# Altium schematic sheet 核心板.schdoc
size 420 x 297 mm; Symbol: Drawing-Symbol_A4; Company: 嘉立创EDA; Version: V1.0; Page Size: A4; @Project Name: 短信息编辑器; @Update Date: 2026-06-04; @Create Date: 2026-06-04; Device: Drawing-Symbol_A4; @Board Name: Board1; @Page Name: P1; @Create Time: 14:51:12; @Page Count: 1; @Page No: 1; @Schematic Name: Schematic1; @Update Time: 14:51:12; @Assembly Variant: Basic; Border: 1; Title Block Position: 3; Size: A4; Width: 1655; Height: 1170; Region Start: 1; X Region Count: 6; Y Region Count: 4; Blade Width: 10
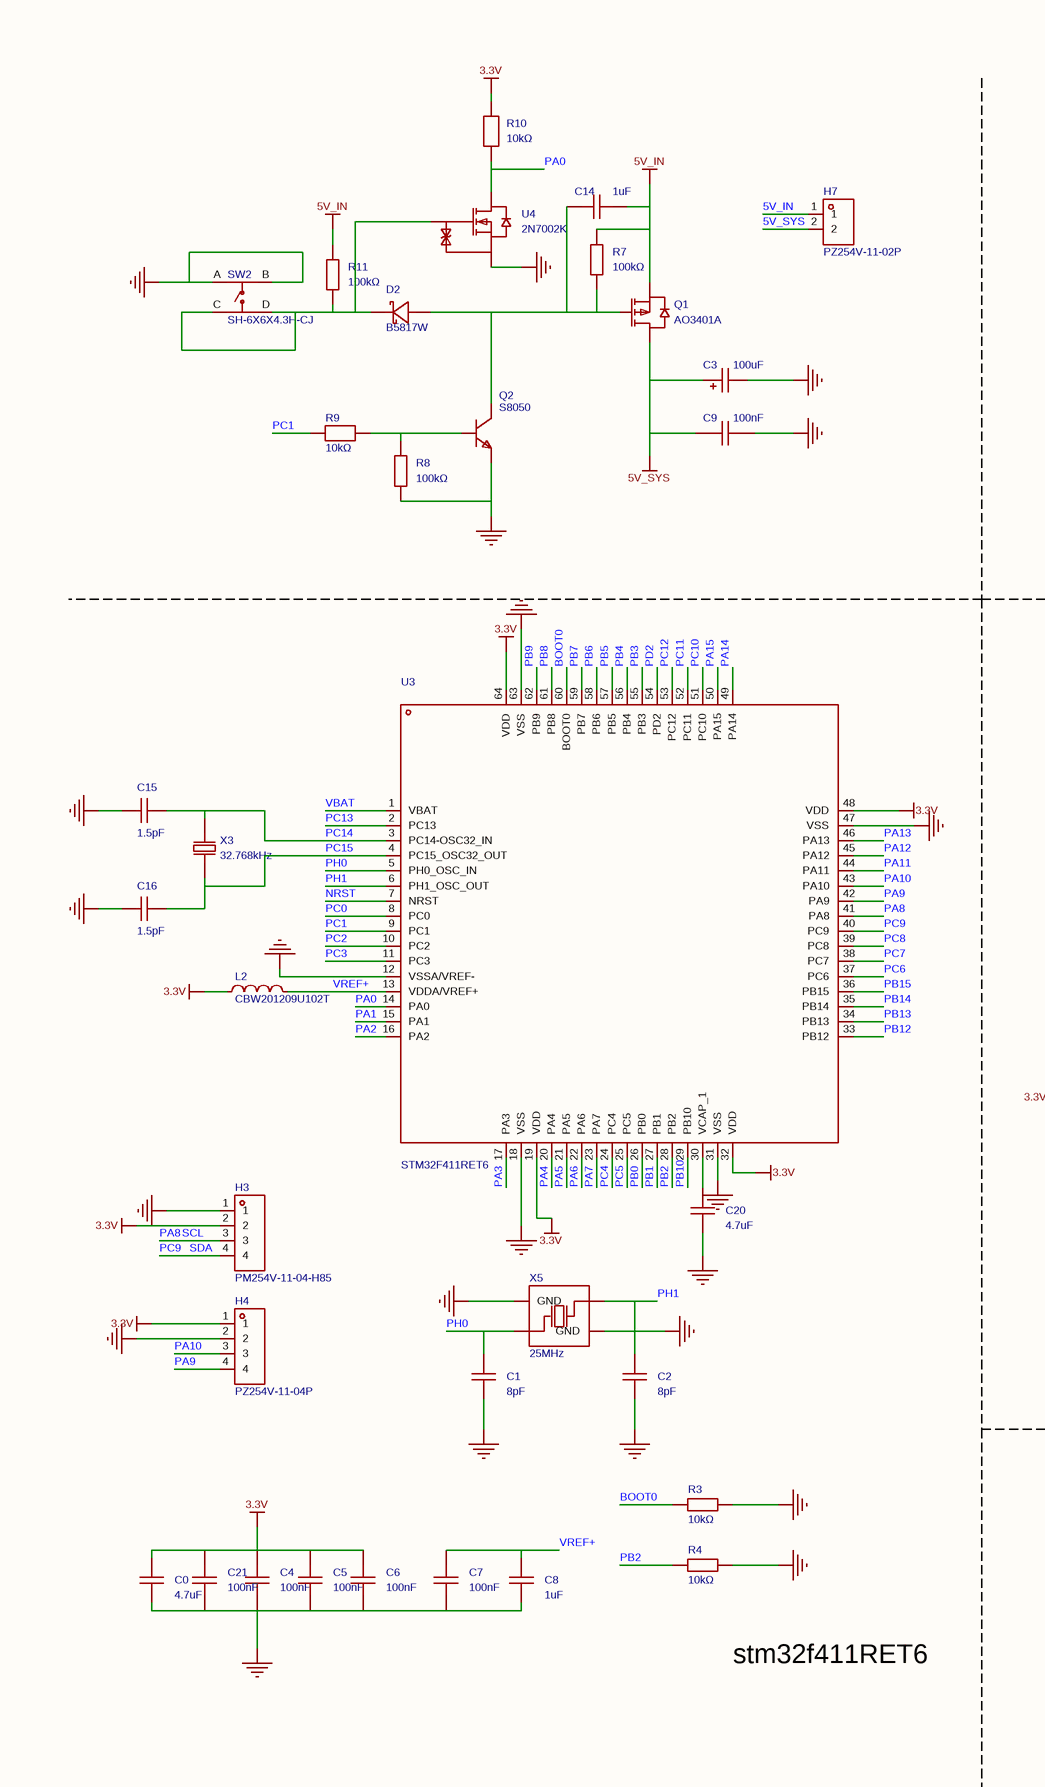
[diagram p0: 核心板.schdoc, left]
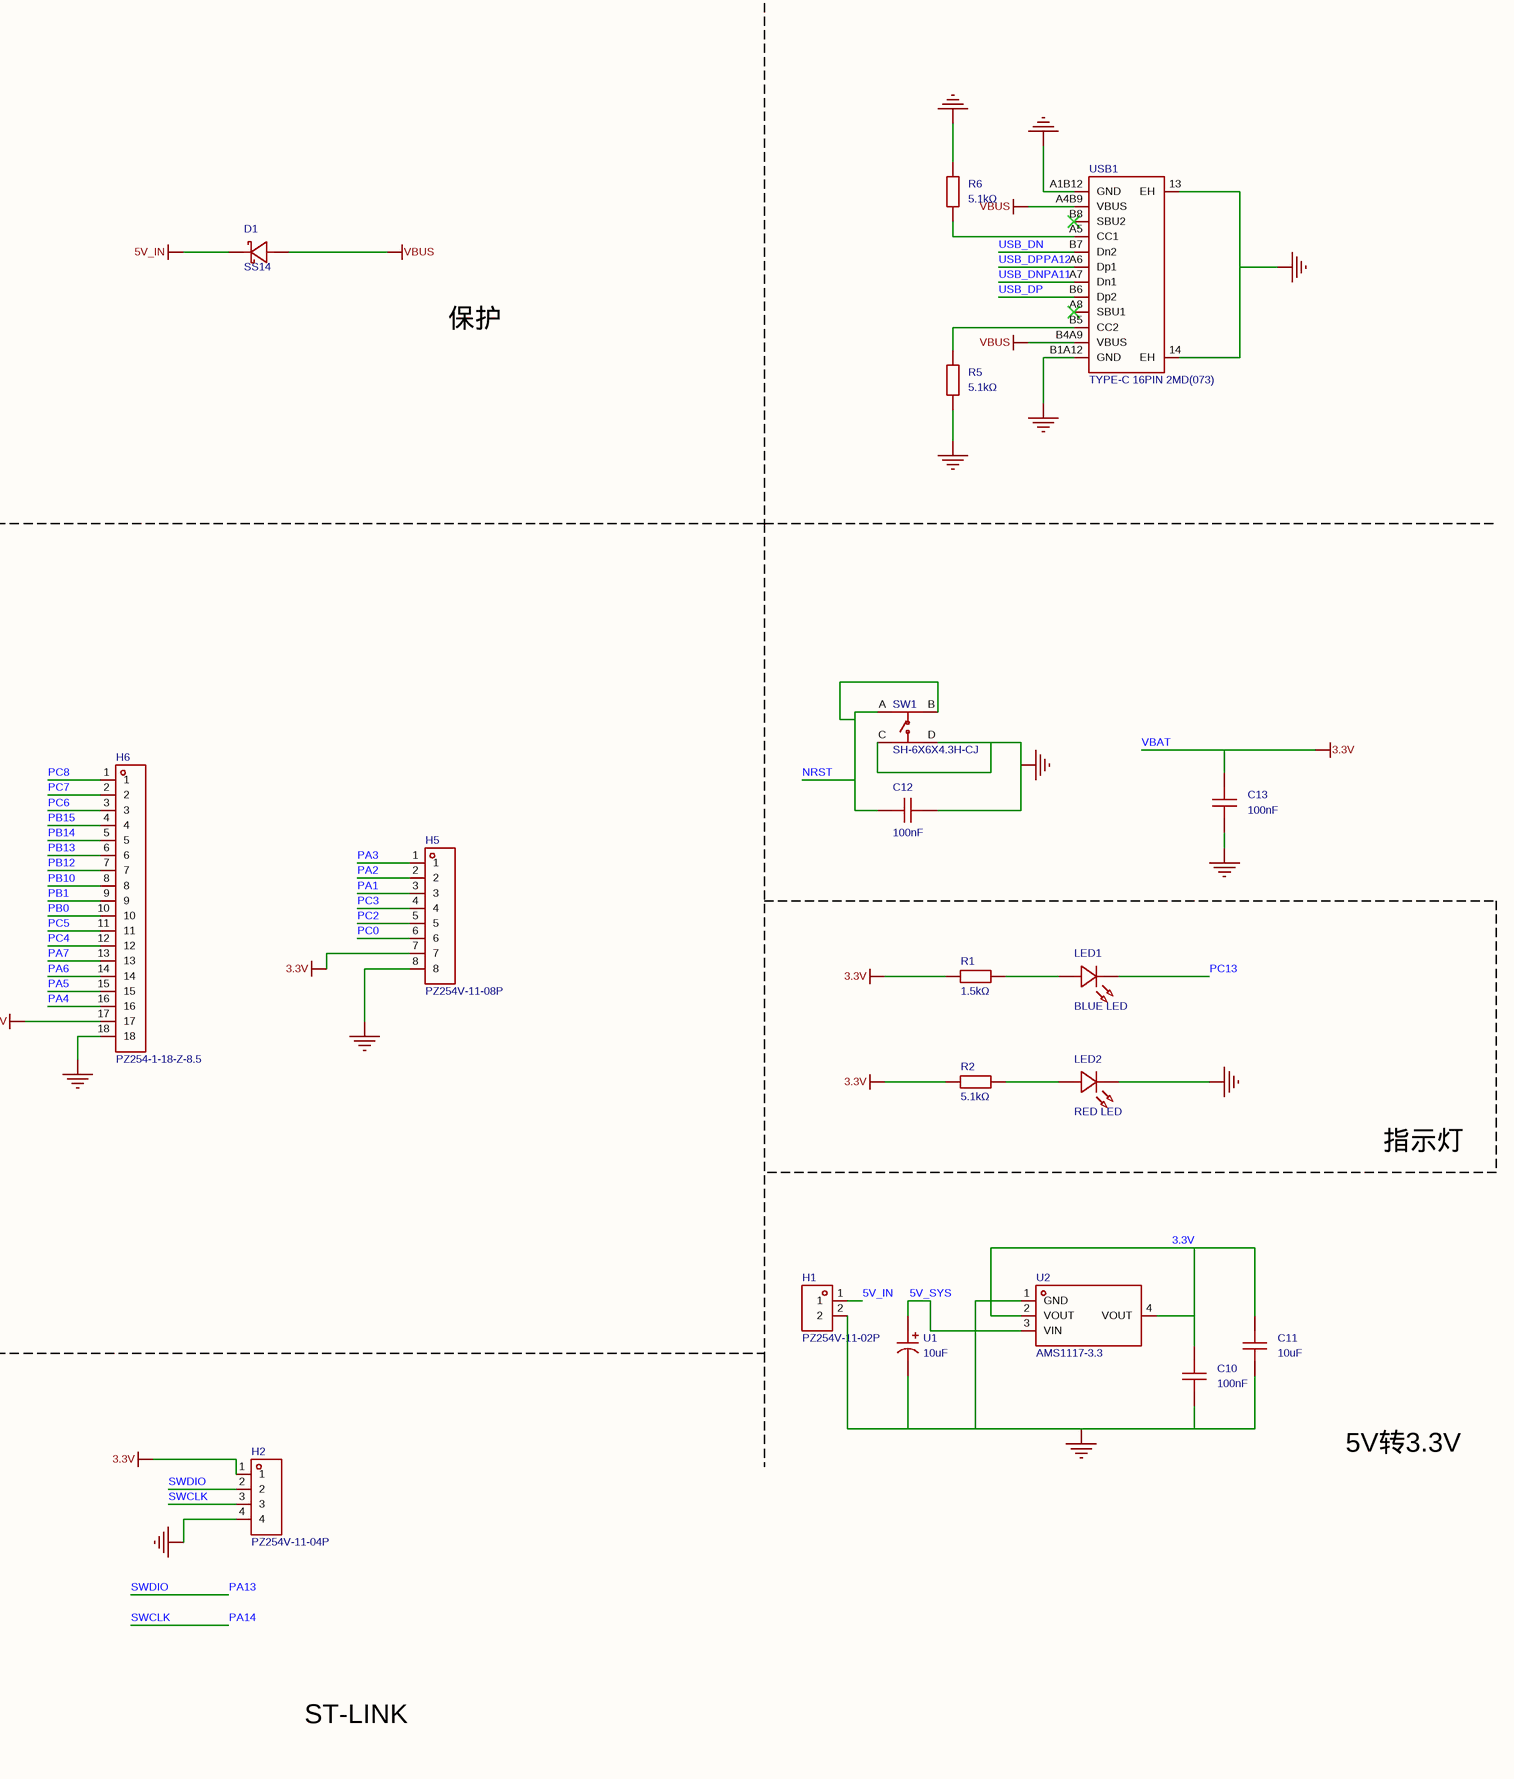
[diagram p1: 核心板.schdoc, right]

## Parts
C0  4.7uF  [C0805]
C1  8pF  [C0603]
C2  8pF  [C0603]
C3  100uF  [CASE-B_3528]
C4  100nF  [C0805]
C5  100nF  [C0805]
C6  100nF  [C0805]
C7  100nF  [C0805]
C8  1uF  [C0805]
C9  100nF  [C0805]
C10  100nF  [C0805]
C11  10uF  [C0805]
C12  100nF  [C0805]
C13  100nF  [C0805]
C14  1uF  [C0805]
C15  1.5pF  [C0603]
C16  1.5pF  [C0603]
C20  4.7uF  [C0805]
C21  100nF  [C0805]
D1  SS14  [SMA_L4.3-W2.6-LS5.0-FD]
D2  B5817W  [SOD-123_L2.7-W1.6-LS3.7-FD]
H1  PZ254V-11-02P  [HDR-TH_2P-P2.54-V-M]
H2  PZ254V-11-04P  [HDR-TH_4P-P2.54-V-M]
H3  PM254V-11-04-H85  [HDR-TH_4P-P2.54-V-F]
H4  PZ254V-11-04P  [HDR-TH_4P-P2.54-V-M]
H5  PZ254V-11-08P  [HDR-TH_8P-P2.54-V-M]
H6  PZ254-1-18-Z-8.5  [HDR-TH_18P-P2.54-V-M]
H7  PZ254V-11-02P  [HDR-TH_2P-P2.54-V-M]
L2  CBW201209U102T  [L0805]
LED1  BLUE LED  [LED0805-RD_BLUE]
LED2  RED LED  [LED0805-R-RD_RED]
Q1  AO3401A  [SOT-23_L2.9-W1.3-P1.90-LS2.4-BR]
Q2  S8050  [SOT-23-3_L2.9-W1.3-P1.90-LS2.3-BR]
R1  1.5kΩ  [R0805]
R2  5.1kΩ  [R0805]
R3  10kΩ  [R0805]
R4  10kΩ  [R0805]
R5  5.1kΩ  [R0805]
R6  5.1kΩ  [R0805]
R7  100kΩ  [R0805]
R8  100kΩ  [R0805]
R9  10kΩ  [R0805]
R10  10kΩ  [R0805]
R11  100kΩ  [R0805]
SW1  SH-6X6X4.3H-CJ  [SW-TH_SH-6X6X4.3H-CJ]
SW2  SH-6X6X4.3H-CJ  [SW-TH_SH-6X6X4.3H-CJ]
U1  10uF  [CAP-SMD_L2.0-W1.3-FD]
U2  AMS1117-3.3  [SOT-223-3_L6.5-W3.4-P2.30-LS7.0-BR]
U3  STM32F411RET6  [LQFP-64_L10.0-W10.0-P0.50-LS12.0-BL]
U4  2N7002K  [SOT-23-3_L2.9-W1.3-P0.95-LS2.4-BR]
USB1  TYPE-C 16PIN 2MD(073)  [USB-C-SMD_TYPE-C-16PIN-2MD-073]
X3  32.768kHz  [CRYSTAL-SMD_L3.2-W1.5-1]
X5  25MHz  [CRYSTAL-SMD_4P-L3.2-W2.5-BL]

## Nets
3.3V: C0.2 C4.2 C5.2 C6.2 C10.2 C11.2 C13.2 C21.2 H2.1 H3.2 H4.1 H5.7 H6.17 L2.1 R1.1 R2.1 R10.2 U2.2(VOUT) U2.4(VOUT) U3.1(VBAT) U3.19(VDD) U3.32(VDD) U3.48(VDD) U3.64(VDD)  [also labelled VBAT]
5V_IN: C14.1 D1.2(K) H1.1 H7.1 Q1.2(S) R7.2 R11.2
5V_SYS: C3.1 C9.2 H7.2 Q1.3(D) U1.1 U2.3(VIN)
GND: C0.1 C1.1 C2.1 C3.2 C4.1 C5.1 C6.1 C7.1 C8.1 C9.1 C10.1 C11.1 C12.1 C13.1 C15.1 C16.1 C20.1 C21.1 H1.2 H2.4 H3.1 H4.2 H5.8 H6.18 LED2.2(C) Q2.2(E) R3.2 R4.2 R5.1 R6.2 R8.1 SW1.C SW1.D SW2.A SW2.B U1.2 U2.1(GND) U3.12(VSSA/VREF-) U3.18(VSS) U3.31(VSS) U3.47(VSS) U3.63(VSS) U4.2(S) USB1.13(EH) USB1.14(EH) USB1.A1B12(GND) USB1.B1A12(GND) X5.2(GND) X5.4(GND)
VBUS: D1.1(A) USB1.A4B9(VBUS) USB1.B4A9(VBUS)
BOOT0: R3.1 U3.60(BOOT0)
NRST: C12.2 SW1.A SW1.B U3.7(NRST)
PA0: R10.1 U3.14(PA0) U4.3(D)
PA1: H5.3 U3.15(PA1)
PA2: H5.2 U3.16(PA2)
PA3: H5.1 U3.17(PA3)
PA4: H6.16 U3.20(PA4)
PA5: H6.15 U3.21(PA5)
PA6: H6.14 U3.22(PA6)
PA7: H6.13 U3.23(PA7)
PA8: H3.3 U3.41(PA8)  [also labelled SCL]
PA9: H4.4 U3.42(PA9)
PA10: H4.3 U3.43(PA10)
PA11: U3.44(PA11) USB1.A7(Dn1) USB1.B7(Dn2)  [also labelled USB_DN]
PA12: U3.45(PA12) USB1.A6(Dp1) USB1.B6(Dp2)  [also labelled USB_DP]
PA13: H2.2 U3.46(PA13)  [also labelled SWDIO]
PA14: H2.3 U3.49(PA14)  [also labelled SWCLK]
PA15: U3.50(PA15)
PB0: H6.10 U3.26(PB0)
PB1: H6.9 U3.27(PB1)
PB2: R4.1 U3.28(PB2)
PB3: U3.55(PB3)
PB4: U3.56(PB4)
PB5: U3.57(PB5)
PB6: U3.58(PB6)
PB7: U3.59(PB7)
PB8: U3.61(PB8)
PB9: U3.62(PB9)
PB10: H6.8 U3.29(PB10)
PB12: H6.7 U3.33(PB12)
PB13: H6.6 U3.34(PB13)
PB14: H6.5 U3.35(PB14)
PB15: H6.4 U3.36(PB15)
PC0: H5.6 U3.8(PC0)
PC1: R9.1 U3.9(PC1)
PC2: H5.5 U3.10(PC2)
PC3: H5.4 U3.11(PC3)
PC4: H6.12 U3.24(PC4)
PC5: H6.11 U3.25(PC5)
PC6: H6.3 U3.37(PC6)
PC7: H6.2 U3.38(PC7)
PC8: H6.1 U3.39(PC8)
PC9: H3.4 U3.40(PC9)  [also labelled SDA]
PC10: U3.51(PC10)
PC11: U3.52(PC11)
PC12: U3.53(PC12)
PC13: LED1.1(K) U3.2(PC13)
PC14: C15.2 U3.3(PC14-OSC32_IN) X3.2
PC15: C16.2 U3.4(PC15_OSC32_OUT) X3.1
PD2: U3.54(PD2)
PH0: C1.2 U3.5(PH0_OSC_IN) X5.1(OSC1)
PH1: C2.2 U3.6(PH1_OSC_OUT) X5.3(OSC2)
VREF+: C7.2 C8.2 L2.2 U3.13(VDDA/VREF+)
NetC14_2: C14.2 D2.1(A) Q1.1(G) Q2.3(C) R7.1
NetC20_2: C20.2 U3.30(VCAP_1)
NetD2_2: D2.2(K) R11.1 SW2.C SW2.D U4.1(G)
NetLED1_2: LED1.2(A) R1.2
NetLED2_1: LED2.1(A) R2.2
NetQ2_1: Q2.1(B) R8.2 R9.2
NetR5_2: R5.2 USB1.B5(CC2)
NetR6_1: R6.1 USB1.A5(CC1)

Not connected (* = marked no-connect by the designer): USB1 A8(SBU1)* B8(SBU2)*

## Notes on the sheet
- 保护
- 指示灯
- 5V转3.3V
- stm32f411RET6
- ST-LINK

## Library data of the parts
C0 C20 = CL21A475KAQNNNE: 容值:4.7uF;精度:±10%;额定电压:25V;温度系数:X5R;; Manufacturer: SAMSUNG(三星); AddInBom: yes; ModelId: 1ba041120af144c991958decab20d2410819f05c4eef4c71ace90d822a990e87; ModelName: C0805_L2.0-W1.3-H1.3; ModelTransform: 78.74,51.181,0,0,0,0,0,0.0005,0; Tolerance: ±10%; Voltage Rating: 25V; Temperature Coefficient: X5R
C1 C2 = 0603CG8R0C500NT: 容值:8pF;额定电压:50V;温度系数:C0G;; Manufacturer: FH(风华); Symbol: 0603CG8R0C500NT_C36508; AddInBom: yes; ModelId: ac125912035d415993ca9572d50418b10819f05c4eef4c71ace90d822a990e87; ModelName: C0603_L1.6-W0.8-H0.8; ModelTransform: 62.992,31.496,0,0,0,0,0,0,0; Voltage Rating: 50V; Temperature Coefficient: C0G
C3 = TAJB107K006RNJ: 容值:100uF;精度:±10%;额定电压:6.3V;等效串联电阻(ESR):1.7Ω@100kHz;; Manufacturer: Kyocera AVX; AddInBom: yes; ModelId: b77bd53aeda446d2bdd09b0fdaf9418a0819f05c4eef4c71ace90d822a990e87; ModelName: CASE-B_L3.5-W2.8-H1.9; ModelTransform: 145.669,110.236,0,0,0,0,0,0,0; Tolerance: ±10%; Voltage Rating: 6.3V
C4-C7 C10 C12 C13 = CL21B104KBCNNNC: 容值:100nF;精度:±10%;额定电压:50V;温度系数:X7R;; Manufacturer: SAMSUNG(三星); AddInBom: yes; ModelId: 1ba041120af144c991958decab20d2410819f05c4eef4c71ace90d822a990e87; ModelName: C0805_L2.0-W1.3-H1.3; ModelTransform: 78.74,51.181,0,0,0,0,0,0.0005,0; Tolerance: ±10%; Voltage Rating: 50V; Temperature Coefficient: X7R
C8 = CL21B105KAFNNNE: 容值:1uF;精度:±10%;额定电压:25V;温度系数:X7R;; Manufacturer: SAMSUNG(三星); AddInBom: yes; ModelId: 1ba041120af144c991958decab20d2410819f05c4eef4c71ace90d822a990e87; ModelName: C0805_L2.0-W1.3-H1.3; ModelTransform: 78.74,51.181,0,0,0,0,0,0.0005,0; Tolerance: ±10%; Voltage Rating: 25V; Temperature Coefficient: X7R
C9 C21 = CL21B104KBCNNNC: 容值:100nF;精度:±10%;额定电压:50V;温度系数:X7R;; Manufacturer: SAMSUNG(三星); 3D Model: 1ba041120af144c991958decab20d2410819f05c4eef4c71ace90d822a990e87; 3D Model Transform: 78.74,51.181,0,0,0,0,0,0.0005,0; Tolerance: ±10%; Voltage Rating: 50V; Temperature Coefficient: X7R; AddInBom: yes; ModelName: C0805_L2.0-W1.3-H1.3
C11 = CGA0805X5R106K500MT: 容值:10uF;精度:±10%;额定电压:50V;温度系数:X5R;; Manufacturer: HRE(芯声); AddInBom: yes; ModelId: 1ba041120af144c991958decab20d2410819f05c4eef4c71ace90d822a990e87; ModelName: C0805_L2.0-W1.3-H1.3; ModelTransform: 78.74,51.181,0,0,0,0,0,0.0005,0; Tolerance: ±10%; Voltage Rating: 50V; Temperature Coefficient: X5R
C14 = CGA0805X7R105K500MT: 容值:1uF;精度:±10%;额定电压:50V;温度系数:X7R;; Manufacturer: HRE(芯声); AddInBom: yes; ModelId: 1ba041120af144c991958decab20d2410819f05c4eef4c71ace90d822a990e87; ModelName: C0805_L2.0-W1.3-H1.3; ModelTransform: 78.74,51.181,0,0,0,0,0,0.0005,0; Tolerance: ±10%; Voltage Rating: 50V; Temperature Coefficient: X7R
C15 C16 = 0603CG1R5C500NT: 容值:1.5pF;额定电压:50V;温度系数:C0G;; Manufacturer: FH(风华); AddInBom: yes; ModelId: ac125912035d415993ca9572d50418b10819f05c4eef4c71ace90d822a990e87; ModelName: C0603_L1.6-W0.8-H0.8; ModelTransform: 62.992,31.496,0,0,0,0,0,0,0; Voltage Rating: 50V; Temperature Coefficient: C0G
D1 = SS14_C7420316: 二极管配置:独立式;正向压降(Vf):550mV@1.0A;直流反向耐压(Vr):40V;整流电流:1A;; Manufacturer: R+O(宏嘉诚); AddInBom: yes; ModelId: 7e24bebe6cd74171ae8c9de6fc5b78aa0819f05c4eef4c71ace90d822a990e87; ModelTransform: 198.4248,103.5431,0,180,0,0,-0.001,0,0; Diode Configuration: 独立式; Voltage - DC Reverse(Vr): 40V; Current - Rectified: 1A; Reverse Leakage Current (Ir): 200uA@40V; Operating Junction Temperature Range: -55℃~+150℃; Non-Repetitive Peak Forward Surge Current: 30A
D2 = B5817W_C7420328: 二极管配置:独立式;正向压降(Vf):450mV@1.0A;直流反向耐压(Vr):20V;整流电流:1A;; Manufacturer: R+O(宏嘉诚); AddInBom: yes; ModelId: 5054d9b7be8b429dad093a54b517b4dd0819f05c4eef4c71ace90d822a990e87; ModelTransform: 145.669,61.024,0,0,0,0,0,0,0; Diode Configuration: 独立式; Voltage - DC Reverse(Vr): 20V; Current - Rectified: 1A; Reverse Leakage Current (Ir): 1mA@20V; Operating Junction Temperature Range: -55℃~+150℃
H1 = PZ254V-11-02P: 插针结构:1x2P;间距:2.54mm;行距:-;圆针/方针:方针;安装方式:直插;排数:单排;总PIN位数:2P;额定电流:3A;额定电压:250V;配合针长度:6mm;塑高:2.5mm;端接针长度:3mm;触头材质:黄铜;触头镀层:-;工作温度:-40℃~+105℃;颜色:黑色;; Manufacturer: XFCN(兴飞); AddInBom: yes; ModelId: e35305ec3aa84b66b849f914b715e73f0819f05c4eef4c71ace90d822a990e87; ModelName: HDR2.54-M-LI-1X2P; ModelTransform: 200,100,0,0,0,0,0,0,-118.11; Pin Structure: 1x2P; Pitch: 2.54mm; Circluar Pins/Square Pins: 方针; Current Rating: 3A; Voltage Rating (Max): 250V
H2 = PZ254V-11-04P: 插针结构:1x4P;间距:2.54mm;行距:-;圆针/方针:方针;安装方式:直插;排数:单排;总PIN位数:4P;额定电流:3A;额定电压:250V;配合针长度:6mm;塑高:2.5mm;端接针长度:3mm;触头材质:-;工作温度:-40℃~+105℃;颜色:黑色;; Manufacturer: XFCN(兴飞); Symbol: PZ254V-11-04P_C2691448; AddInBom: yes; ModelId: 112f4d05e8d64e99ab9a333894bea4f90819f05c4eef4c71ace90d822a990e87; ModelName: HDR-TH_4P-P2.54-M-LI-1X4P; ModelTransform: 399.999,104.7242,0,0,0,0,0,0,-118.11; Pin Structure: 1x4P; Pitch: 2.54mm; Circluar Pins/Square Pins: 方针; Current Rating: 3A; Voltage Rating (Max): 250V
H3 = PM254V-11-04-H85: 插孔结构:1x4P;间距:2.54mm;行距:-;圆孔/方孔:方孔;安装方式:直插;排数:单排;总孔位数:4P;额定电流:3A;插孔方向:顶部;塑高:8.5mm;触头材质:黄铜;触头镀层:-;工作温度:-40℃~+105℃;; Manufacturer: XFCN(兴飞); AddInBom: yes; ModelId: d187812051054f85879fcaa51a310d8e0819f05c4eef4c71ace90d822a990e87; ModelTransform: 419.6842,98.464,0,0,0,0,0,0,-118.11; Holes Structure: 1x4P; Pitch: 2.54mm; Circular Hole / Square Hole: 方孔; Number of Positions: 4P; Current Rating: 3A; Holes Direction: 顶部
H4 = PZ254V-11-04P: 插针结构:1x4P;间距:2.54mm;行距:-;圆针/方针:方针;安装方式:直插;排数:单排;总PIN位数:4P;额定电流:3A;额定电压:250V;配合针长度:6mm;塑高:2.5mm;端接针长度:3mm;触头材质:-;工作温度:-40℃~+105℃;颜色:黑色;; Manufacturer: XFCN(兴飞); Symbol: PZ254V-11-04P_C2691448; 3D Model: 112f4d05e8d64e99ab9a333894bea4f90819f05c4eef4c71ace90d822a990e87; 3D Model Transform: 399.999,104.7242,0,0,0,0,0,0,-118.11; Pin Structure: 1x4P; Pitch: 2.54mm; Circluar Pins/Square Pins: 方针; Current Rating: 3A; Voltage Rating (Max): 250V; AddInBom: yes; ModelName: HDR-TH_4P-P2.54-M-LI-1X4P
H5 = PZ254V-11-08P: 插针结构:1x8P;间距:2.54mm;行距:-;圆针/方针:方针;安装方式:直插;排数:单排;总PIN位数:8P;额定电流:3A;额定电压:250V;配合针长度:6mm;塑高:2.5mm;端接针长度:3mm;触头材质:黄铜;触头镀层:-;工作温度:-40℃~+105℃;颜色:黑色;; Manufacturer: XFCN(兴飞); AddInBom: yes; ModelId: f5b96e27511e49e38545e53df23202020819f05c4eef4c71ace90d822a990e87; ModelTransform: 807.87244,98.425,0,0,0,0,0,0,-118.11; Pin Structure: 1x8P; Pitch: 2.54mm; Circluar Pins/Square Pins: 方针; Current Rating: 3A; Voltage Rating (Max): 250V
H6 = PZ254-1-18-Z-8.5: 插针结构:1x18P;间距:2.54mm;行距:-;圆针/方针:方针;安装方式:直插;排数:单排;总PIN位数:18P;额定电流:3A;额定电压:-;配合针长度:6mm;塑高:2.5mm;端接针长度:3mm;触头材质:黄铜;工作温度:-40℃~+105℃;颜色:黑色;; Manufacturer: HCTL(华灿天禄); AddInBom: yes; ModelId: dcddb7416c574af4a634706c3d4050080819f05c4eef4c71ace90d822a990e87; ModelName: HDR-TH_18P-P2.54-M-LI-1X18P; ModelTransform: 1799.99648,98.425,0,0,0,0,0,0,-118.11; Pin Structure: 1x18P; Pitch: 2.54mm; Circluar Pins/Square Pins: 方针; Current Rating: 3A
H7 = PZ254V-11-02P: 插针结构:1x2P;间距:2.54mm;行距:-;圆针/方针:方针;安装方式:直插;排数:单排;总PIN位数:2P;额定电流:3A;额定电压:250V;配合针长度:6mm;塑高:2.5mm;端接针长度:3mm;触头材质:黄铜;触头镀层:-;工作温度:-40℃~+105℃;颜色:黑色;; Manufacturer: XFCN(兴飞); 3D Model: e35305ec3aa84b66b849f914b715e73f0819f05c4eef4c71ace90d822a990e87; 3D Model Transform: 200,100,0,0,0,0,0,0,-118.11; Pin Structure: 1x2P; Pitch: 2.54mm; Circluar Pins/Square Pins: 方针; Current Rating: 3A; Voltage Rating (Max): 250V; AddInBom: yes; ModelName: HDR2.54-M-LI-1X2P
L2 = CBW201209U102T: 阻抗@频率:1kΩ@100MHz;误差:±25%;直流电阻(DCR):250mΩ;; Manufacturer: FH(风华); 3D Model: 37a81e68749a4138bd2dfa6897b24b850819f05c4eef4c71ace90d822a990e87; 3D Model Transform: 78.74,51.181,0,0,0,0,0,0.001,0; Tolerance: ±25%; DC Resistance(DCR): 250mΩ; Current Rating: 1A; Number of Circuits: 1; AddInBom: yes; ModelName: R0805_L2.0-W1.3-H0.6
LED1 = GL0805UB01: 灯头类型:2mmx1.25mm方形灯头;发光颜色:蓝色;正向压降(Vf):3.1V;功率:-;正向电流:20mA；5mA;波长:457nm~475nm;二极管配置:独立二极管;透镜颜色:无色透明透镜;色温:-;发光强度:80mcd;发光角度:120°;载带方式:正贴;工作温度:-40℃~+85℃;; Manufacturer: Guiguang light(桂光光电); AddInBom: yes; ModelId: 6ccd75a2b5134d6ab756ecf3c14a72900819f05c4eef4c71ace90d822a990e87; ModelName: LED0805-RD; ModelTransform: 79.527,49.2125,0,0,0,0,0,0,0; Illumination Color: 蓝色; Voltage - Forward(Vf): 3.1V; Diode Configuration: 独立二极管; Lens Color: 无色透明透镜; Luminous Intensity: 80mcd; Viewing Angle: 120°
LED2 = GL0805UR01: 灯头类型:2mmx1.25mm方形灯头;发光颜色:红色;正向压降(Vf):2.1V;功率:-;正向电流:20mA;波长:618nm~624nm;二极管配置:独立二极管;透镜颜色:无色透明透镜;色温:-;发光强度:100mcd;发光角度:120°;载带方式:正贴;工作温度:-40℃~+85℃;; Manufacturer: Guiguang light(桂光光电); AddInBom: yes; ModelId: f010e90d36544999ab4e363fdba5b4900819f05c4eef4c71ace90d822a990e87; ModelTransform: 78.74,49.21644,0,0,0,0,0,0,0; Illumination Color: 红色; Voltage - Forward(Vf): 2.1V; Forward Current: 20mA; Diode Configuration: 独立二极管; Lens Color: 无色透明透镜; Luminous Intensity: 100mcd; Viewing Angle: 120°
Q1 = AO3401A_C347476: 数量:1个P沟道;漏源电压(Vdss):30V;连续漏极电流(Id):4.2A;导通电阻(RDS(on)):50mΩ@10V;耗散功率(Pd):1.4W;阈值电压(Vgs(th)):1.3V@250uA;; Manufacturer: UMW(友台半导体); AddInBom: yes; ModelId: c62791f0466c4ae2a892c056b845b0ca0819f05c4eef4c71ace90d822a990e87; ModelName: SOT-23-3P_L2.9-W1.3-H1.0-LS2.4-P0.95; ModelTransform: 98.64468,114.173,0,180,0,0,0.001,-0.002,0; Number: 1个P沟道; Drain to Source Voltage: 30V; Current - Continuous Drain(Id): 4.2A; Pd - Power Dissipation: 1.4W; Gate Charge(Qg): 9.4nC@4.5V; Input Capacitance(Ciss): 954pF; Reverse Transfer Capacitance (Crss@Vds): 77pF; Type: P沟道; Output Capacitance(Coss): 115pF
Q2 = S8050_C20069125: 晶体管类型:NPN;集电极电流(Ic):500mA;集射极击穿电压(Vceo):25V;耗散功率(Pd):300mW;直流电流增益(hFE):120@50mA,1.0V;; Manufacturer: R+O(宏嘉诚); AddInBom: yes; ModelId: 5504beb8757f4de79731898ec55d3e540819f05c4eef4c71ace90d822a990e87; ModelTransform: 114.173,90.551,0,90,0,0,0,0,0; type: NPN; Current - Collector(Ic): 500mA; Collector - Emitter Voltage VCEO: 25V; Pd - Power Dissipation: 300mW; Transition frequency(fT): 100MHz; Current - Collector Cutoff: 100nA; Vce Saturation(VCE(sat)): 600mV@500mA,50mA; Emitter-Base Voltage(Vebo): 5V
R1 = 0805W8F1501T5E: 电阻类型:厚膜电阻;阻值:1.5kΩ;精度:±1%;功率:125mW;最大工作电压:150V;温度系数:±100ppm/℃;; Manufacturer: UNI-ROYAL(厚声); AddInBom: yes; ModelId: 37a81e68749a4138bd2dfa6897b24b850819f05c4eef4c71ace90d822a990e87; ModelName: R0805_L2.0-W1.3-H0.6; ModelTransform: 78.74,51.181,0,0,0,0,0,-0.0005,0; Tolerance: ±1%; Power(Watts): 125mW; Overload Voltage (Max): 150V
R2 R5 R6 = 0805W8F5101T5E: 电阻类型:厚膜电阻;阻值:5.1kΩ;精度:±1%;功率:125mW;工作电压:150V;温度系数:±100ppm/℃;; Manufacturer: UNI-ROYAL(厚声); AddInBom: yes; ModelId: 37a81e68749a4138bd2dfa6897b24b850819f05c4eef4c71ace90d822a990e87; ModelName: R0805_L2.0-W1.3-H0.6; ModelTransform: 78.74,51.181,0,0,0,0,0,-0.0005,0; Tolerance: ±1%; Power(Watts): 125mW; Voltage-Supply(Max): 150V
R3 R4 = 0805W8F1002T5E_C17414: 电阻类型:厚膜电阻;阻值:10kΩ;精度:±1%;功率:125mW;工作电压:150V;温度系数:±100ppm/℃;; Manufacturer: UNI-ROYAL(厚声); AddInBom: yes; ModelId: 37a81e68749a4138bd2dfa6897b24b850819f05c4eef4c71ace90d822a990e87; ModelName: R0805_L2.0-W1.3-H0.6; ModelTransform: 78.74,51.181,0,0,0,0,0,-0.0005,0; Tolerance: ±1%; Power(Watts): 125mW; Voltage-Supply(Max): 150V
R7 R11 = RT0805BRD07100KL: 电阻类型:薄膜电阻;阻值:100kΩ;精度:±0.1%;功率:125mW;最大工作电压:150V;温度系数:±25ppm/℃;; Manufacturer: YAGEO(国巨); 3D Model: 37a81e68749a4138bd2dfa6897b24b850819f05c4eef4c71ace90d822a990e87; 3D Model Transform: 78.74,51.181,0,0,0,0,0,-0.0005,0; Tolerance: ±0.1%; Power(Watts): 125mW; Overload Voltage (Max): 150V; AddInBom: yes; ModelName: R0805_L2.0-W1.3-H0.6
R8 = RT0805BRD07100KL: 电阻类型:薄膜电阻;阻值:100kΩ;精度:±0.1%;功率:125mW;最大工作电压:150V;温度系数:±25ppm/℃;; Manufacturer: YAGEO(国巨); AddInBom: yes; ModelId: 37a81e68749a4138bd2dfa6897b24b850819f05c4eef4c71ace90d822a990e87; ModelName: R0805_L2.0-W1.3-H0.6; ModelTransform: 78.74,51.181,0,0,0,0,0,-0.0005,0; Tolerance: ±0.1%; Power(Watts): 125mW; Overload Voltage (Max): 150V
R9 R10 = FRC0805J103TS: 电阻类型:厚膜电阻;阻值:10kΩ;精度:±5%;功率:125mW;工作电压:150V;温度系数:±100ppm/℃;; Manufacturer: FOJAN(富捷); AddInBom: yes; ModelId: 37a81e68749a4138bd2dfa6897b24b850819f05c4eef4c71ace90d822a990e87; ModelName: R0805_L2.0-W1.3-H0.6; ModelTransform: 78.74,51.181,0,0,0,0,0,-0.0005,0; Tolerance: ±5%; Power(Watts): 125mW; Voltage-Supply(Max): 150V
SW1 SW2 = SH-6X6X4.3H-CJ: 电路结构:单刀单掷;按钮形状:圆形按钮;作用力:2.5N;安装方式:直插;开关长度:6mm;开关宽度:6mm;开关高度:4.3mm;带支架:不带支架;触点电流:50mA;额定电压:12V;带灯:无;工作寿命:10万次;; Manufacturer: SHOU HAN(首韩); AddInBom: yes; ModelId: 7465a1c6ddb3456bb37faad11a123e5a0819f05c4eef4c71ace90d822a990e87; ModelTransform: 236.22,307.086,0,90,0,0,0,0,-137.795; Circuit: 单刀单掷; Actuator Style: 圆形按钮; Operating Force: 2.5N; Switch Height: 4.3mm; with Bracket: 不带支架; Contact Current: 50mA; Voltage Rating: 12V; Actuator/Cap Color: 黑色; With Lamp: 无; Life: 10万次
U1 = TMCP1A106MTRF: 容值:10uF;精度:±20%;额定电压:10V;等效串联电阻:5.9Ω@100kHz;; Manufacturer: VISHAY(威世); AddInBom: yes; ModelId: 1f26856de1634853a779dc49a005d0a10819f05c4eef4c71ace90d822a990e87; ModelTransform: 78.74,49.2125,0,0,0,0,0,-0.551,0; Tolerance: ±20%; Rated Voltage: 10V
U2 = AMS1117-3.3_C6186: 输出类型:固定;工作电压:15V;输出电压:3.3V;输出电流:1A;电源纹波抑制比(PSRR):72dB@(120Hz);输出极性:正极;; Manufacturer: AMS; AddInBom: yes; ModelId: 925194bf9823436183a3e0b978a8d0760819f05c4eef4c71ace90d822a990e87; ModelName: SOT-223-4P_L6.5-W3.5-H1.6-LS7.0-P2.30; ModelTransform: 279.89794,255.905,0,180,0,0,-3.9385,-0.0005,0; Output Type: 固定; Voltage - Supply: 15V; Output Voltage: 3.3V; Output Current: 1A; Voltage Dropout: 1.1V@(800mA); standby current: 5mA; Noise: 0.003%Vout; Output Configuration: 正极; Number of Outputs: 1
U3 = STM32F411RET6: CPU内核:ARM-M4;CPU最大主频:100MHz;应用领域:-;; Manufacturer: ST(意法半导体); AddInBom: yes; ModelId: cd9de06618c44fcf82654c43a457f83c0819f05c4eef4c71ace90d822a990e87; ModelName: LQFP-64_L10.0-W10.0-H1.4-LS12.0-P0.50; ModelTransform: 472.441,472.441,0,0,0,0,0,0.465,0; CPU Core: ARM-M4; CPU Maximum Speed: 100MHz; Program Storage Size: 512KB; Program Memory Type: FLASH; Number of I/O: 50; ADC (Bit): 12bit; Voltage - Supply: 1.7V~3.6V
U4 = 2N7002K_C22379475: 数量:1个N沟道;漏源电压(Vdss):60V;连续漏极电流(Id):340mA;导通电阻(RDS(on)):900mΩ@10V；1.1Ω@4.5V;耗散功率(Pd):350mW;阈值电压(Vgs(th)):1.3V@1.0mA;; Manufacturer: R+O(宏嘉诚); AddInBom: yes; ModelId: c62791f0466c4ae2a892c056b845b0ca0819f05c4eef4c71ace90d822a990e87; ModelName: SOT-23-3P_L2.9-W1.3-H1.0-LS2.4-P0.95; ModelTransform: 98.425,114.173,0,180,0,0,0.0005,-0.0005,0; Number: 1个N沟道; Drain to Source Voltage: 60V; Current - Continuous Drain(Id): 340mA; Pd - Power Dissipation: 350mW; Input Capacitance(Ciss): 40pF@10V; Reverse Transfer Capacitance (Crss@Vds): 10pF@10V
USB1 = TYPE-C 16PIN 2MD(073): 连接器类型:Type-C;协议标准:-;公母:母;安装方式:卧贴;触点数量:16P;端口数量:1;额定电流 - 电源:3A;工作温度:-25℃~+85℃;; Manufacturer: SHOU HAN(首韩); AddInBom: yes; ModelId: 3a41b9ec9b654a0fad4d118405ec62900819f05c4eef4c71ace90d822a990e87; ModelName: USB-C-SMD_TYPE-C-6PIN-2MD-073; ModelTransform: 351.9678,298.4246,0,0,0,0,0,-47.244,-35.433; Gender: 母; Number of Contacts: 16P; Number of Ports: 1; Current Rating-Power: 3A; Voltage Rating: 5V; Connect-Disconnect Life: 1万次; Detection color: 黑色
X3 = Q13FC13500049: 晶振类型:贴片晶振;频率:32.768kHz;常温频差:±20ppm;负载电容:6pF;; Manufacturer: EPSON(爱普生); Symbol: Q13FC1350004900; 3D Model: 762d7afc596f4558a373612390f4386d0819f05c4eef4c71ace90d822a990e87; 3D Model Transform: 125.984,59.055,0,0,0,0,0,0,0; Normal temperature Frequency Tolerance: ±20ppm; Load Capacitance: 6pF; Equivalent Series Resistance(ESR): 70kΩ; AddInBom: yes
X5 = X1E0000210621: 晶振类型:贴片晶振;频率:25MHz;常温频差:±10ppm;负载电容:9pF;; Manufacturer: EPSON(爱普生); AddInBom: yes; ModelId: ff2dfd5650294453a14147960efe18380819f05c4eef4c71ace90d822a990e87; ModelTransform: 125.984,98.425,0,0,0,0,0,0,0; Normal temperature Frequency Tolerance: ±10ppm; Load Capacitance: 9pF; Equivalent Series Resistance(ESR): 40Ω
